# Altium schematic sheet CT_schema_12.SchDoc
size 387 x 278 mm
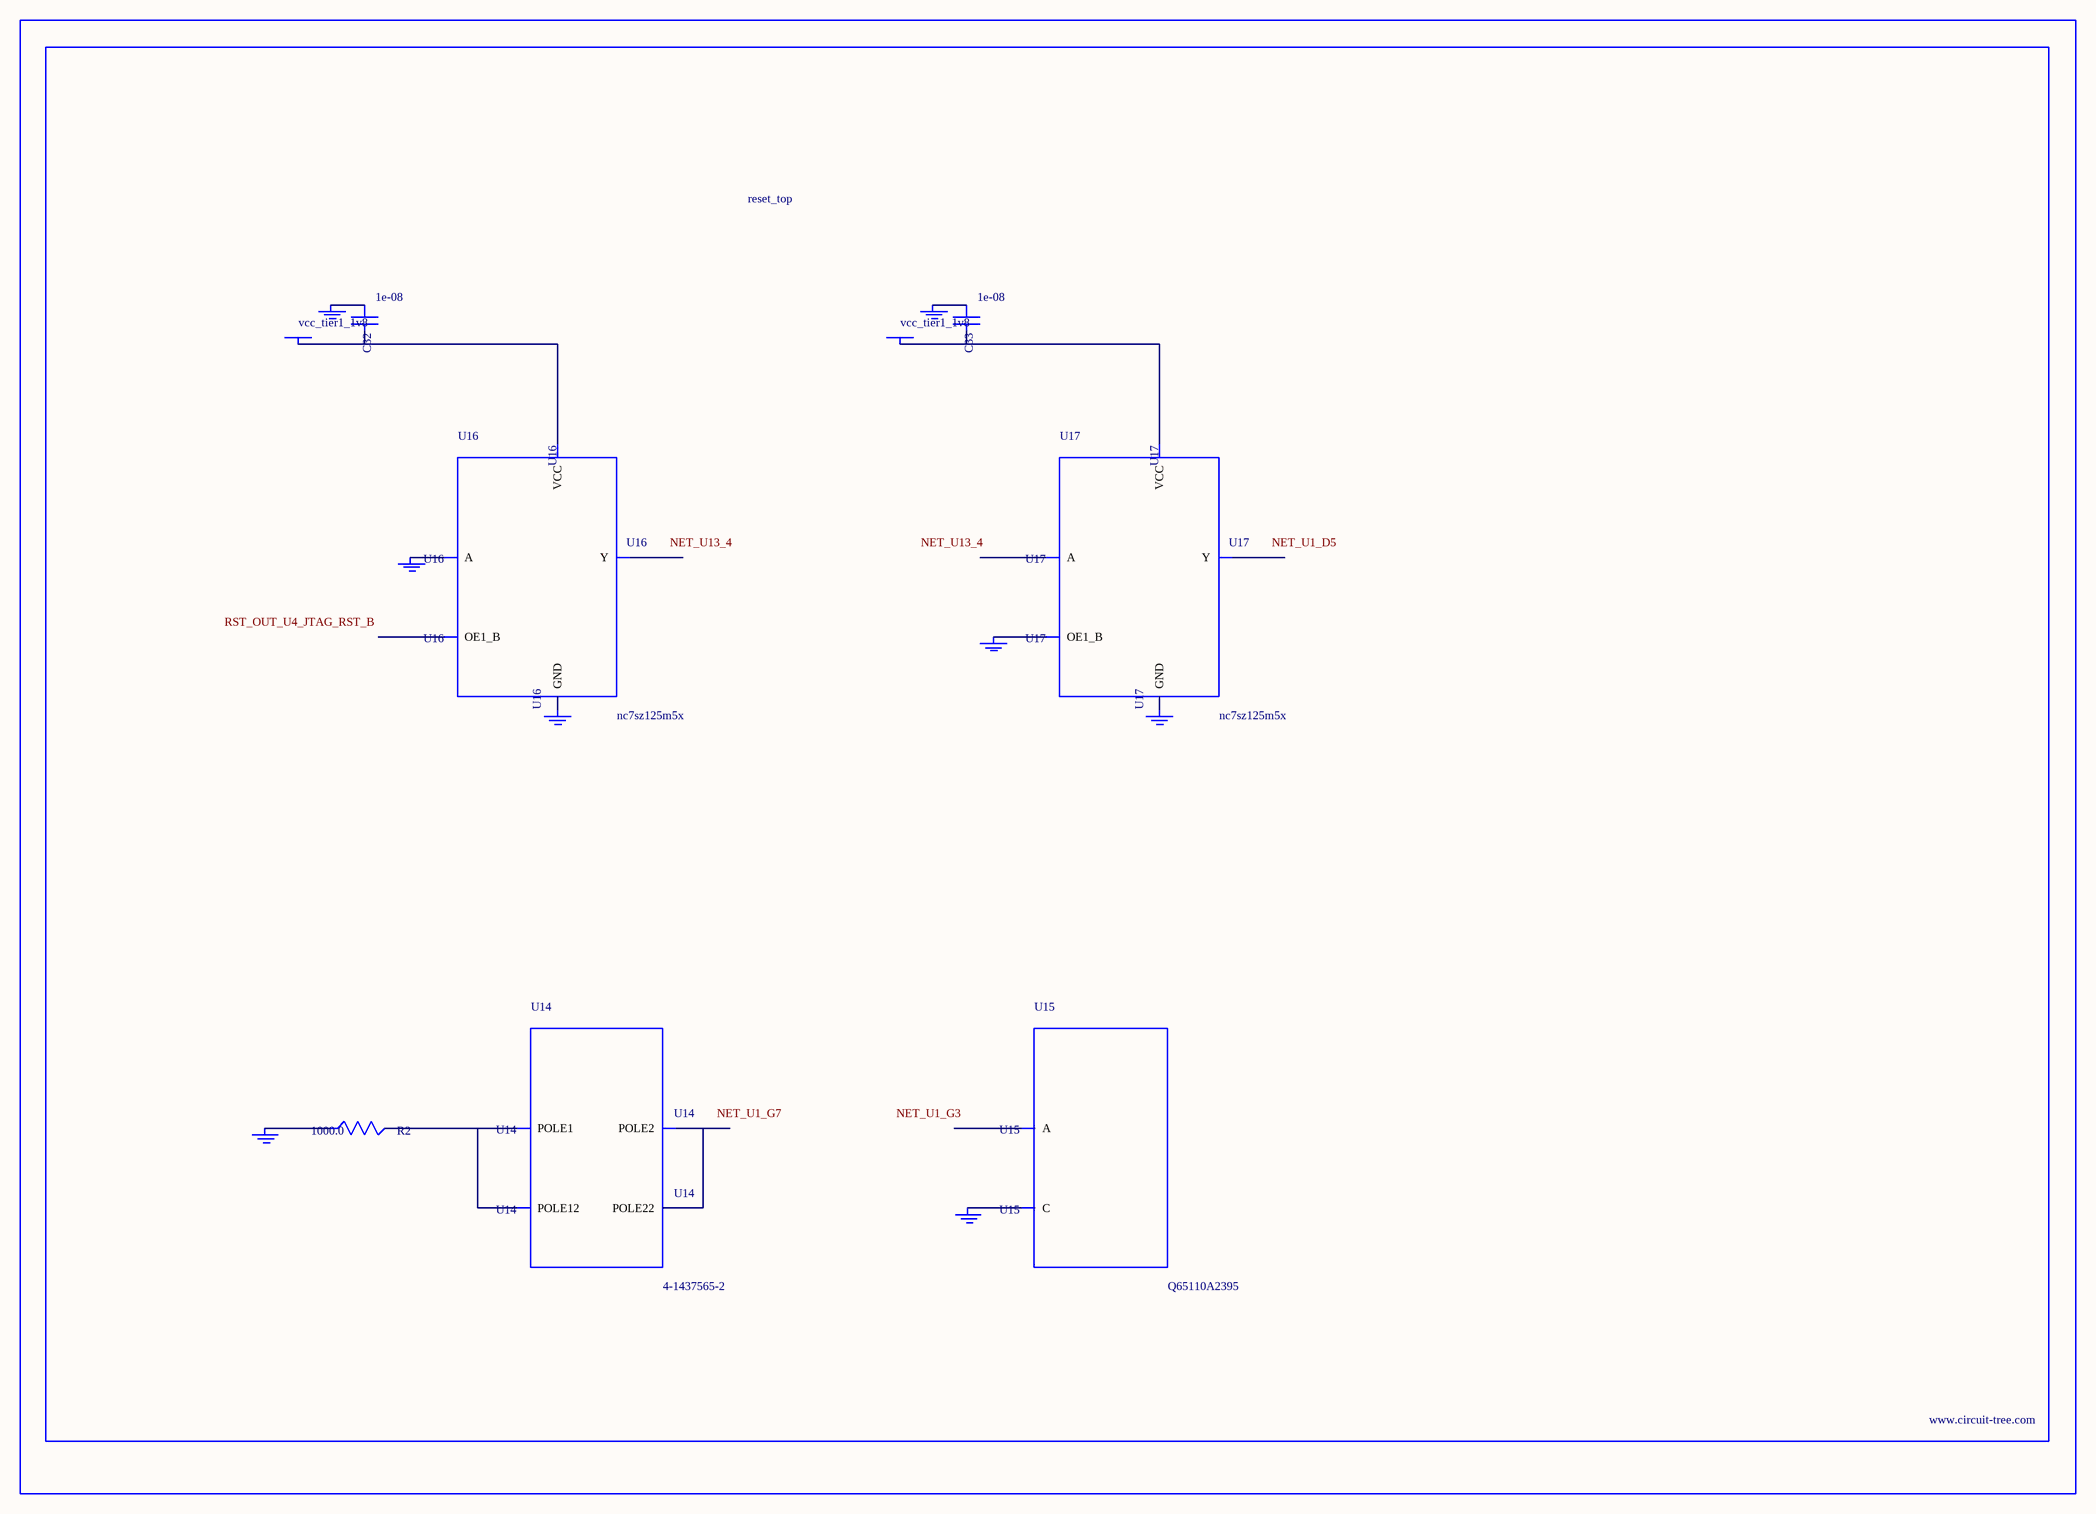
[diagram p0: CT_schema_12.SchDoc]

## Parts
BORDER11  (no value)
C32  1e-08  [C0402]
C33  1e-08  [C0402]
GND_INSTANCE_11_0  (no value)
GND_INSTANCE_11_1  (no value)
GND_INSTANCE_11_2  (no value)
GND_INSTANCE_11_3  (no value)
GND_INSTANCE_11_4  (no value)
GND_INSTANCE_11_5  (no value)
GND_INSTANCE_11_6  (no value)
GND_INSTANCE_11_7  (no value)
POWER_INSTANCE_11_0  vcc_tier1_1v8
POWER_INSTANCE_11_1  vcc_tier1_1v8
R2  1000.0  [R0603]
U14  4-1437565-2  [SW_4-1437565-2]
U15  Q65110A2395  [LGM67K-G1J2-24-Z]
U16  nc7sz125m5x  [NC7SZ125M5X]
U17  nc7sz125m5x  [NC7SZ125M5X]

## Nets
NetC32_1: C32.1 GND_INSTANCE_11_2.0(GND)
NetC32_2: C32.2 POWER_INSTANCE_11_0.0(PWR) U16.5(VCC)
NetC33_1: C33.1 GND_INSTANCE_11_5.0(GND)
NetC33_2: C33.2 POWER_INSTANCE_11_1.0(PWR) U17.5(VCC)
NetGND_INSTANCE_11_0_0: GND_INSTANCE_11_0.0(GND) R2.1
NetGND_INSTANCE_11_1_0: GND_INSTANCE_11_1.0(GND) U15.C
NetGND_INSTANCE_11_3_0: GND_INSTANCE_11_3.0(GND) U16.2(A)
NetGND_INSTANCE_11_4_0: GND_INSTANCE_11_4.0(GND) U16.3(GND)
NetGND_INSTANCE_11_6_0: GND_INSTANCE_11_6.0(GND) U17.1(OE1_B)
NetGND_INSTANCE_11_7_0: GND_INSTANCE_11_7.0(GND) U17.3(GND)
NetR2_2: R2.2 U14.1(POLE1) U14.2(POLE12)
NetU14_3: U14.3(POLE2) U14.4(POLE22)

Not connected (* = marked no-connect by the designer): U15 A; U16 1(OE1_B) 4(Y); U17 2(A) 4(Y)

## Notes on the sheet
- Labels drawn without touching a wire or pin: NET_U1_D5, NET_U1_G3, NET_U1_G7, NET_U13_4, RST_OUT_U4_JTAG_RST_B

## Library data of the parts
BORDER11 = BORDER_PAGE11
C32 C33 = C0402C103K3RAC
GND_INSTANCE_11_0-GND_INSTANCE_11_7 = GND
POWER_INSTANCE_11_0 POWER_INSTANCE_11_1 = PWR
R2 = RC0603JR-071KL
